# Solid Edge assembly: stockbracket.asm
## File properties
Author: Sham
Template: Iso Assembly.asm
Last saved by: TIET
Revision: 5
Application: Solid Edge
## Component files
Stock_support_base.par
thrust_bearing.par
adjusting_screw_nut.par
support_adjusting_screw.par
support_roller_bracket.par
stock_support_roller.par
adjusting_nut_handle.par
adjusting_screw_guide.par
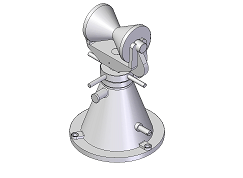
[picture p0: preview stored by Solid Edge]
